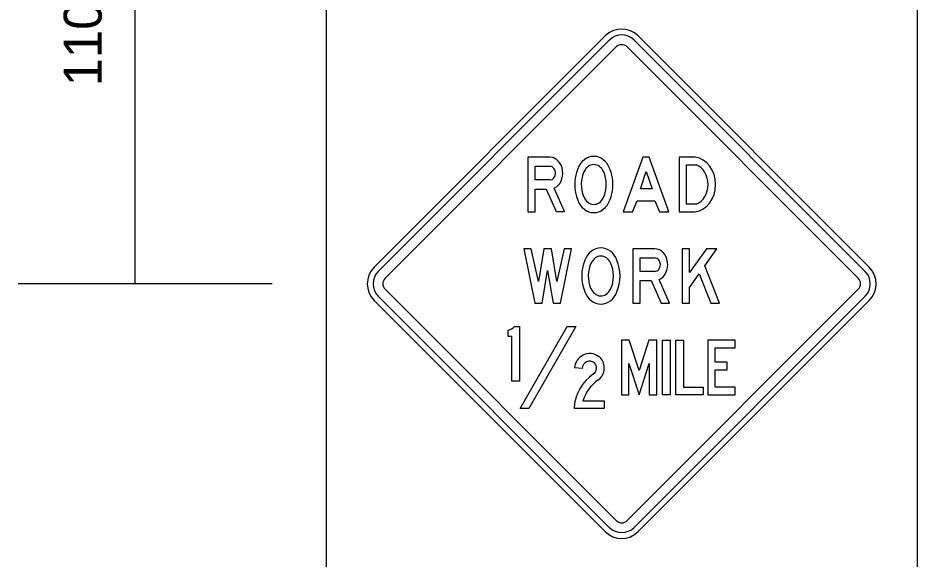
# Model space of a CAD drawing. Extents: x 1531.4 to 1538.6, y 1529.6 to 1539.7.
# Drawn here: x 1536.856 to 1538.277, y 1532.254 to 1533.108 of the extents above; entities that cross this region are included whole.
import ezdxf

# ---------------------------------------------------------------- set-up
doc = ezdxf.new("R2010")
doc.units = 0
for name, color, linetype in [('C-SIGN-FACE-N', 7, 'Continuous'), ('DETL-DIMS', 7, 'Continuous'), ('DETL-LINE', 7, 'Continuous'), ('DETL-NOTE', 7, 'Continuous')]:
    doc.layers.add(name, color=color, linetype=linetype)

msp = doc.modelspace()

# ---------------------------------------------------------------- linework, layer by layer
at = {"layer": 'C-SIGN-FACE-N'}
for p, q in [((1537.784, 1533.0799), (1537.4186, 1532.7145)), ((1538.2015, 1532.7145), (1537.8362, 1533.0799)), ((1537.8626, 1532.7079), (1537.8626, 1532.7079)), ((1537.784, 1532.297), (1537.4186, 1532.6623)), ((1538.2015, 1532.6623), (1537.8362, 1532.297)), ((1537.6308, 1532.6052), (1537.6308, 1532.6151)), ((1537.6308, 1532.6052), (1537.6308, 1532.6151)), ((1537.6308, 1532.6052), (1537.6308, 1532.6151)), ((1537.7474, 1532.5545), (1537.7354, 1532.5556)), ((1537.7474, 1532.5545), (1537.7354, 1532.5556)), ((1537.7474, 1532.5545), (1537.7354, 1532.5556)), ((1537.7474, 1532.5545), (1537.7474, 1532.5545)), ((1537.7474, 1532.5545), (1537.7474, 1532.5545)), ((1537.7474, 1532.5545), (1537.7474, 1532.5545)), ((1537.8297, 1532.3035), (1537.8451, 1532.319))]:
    msp.add_line(p, q, dxfattribs=at)
for points in [[(1537.7905, 1533.0734), (1537.4252, 1532.708)], [(1538.195, 1532.708), (1537.8297, 1533.0734)], [(1537.436, 1532.6971), (1537.8014, 1533.0625)], [(1537.8188, 1533.0625), (1538.1841, 1532.6971)], [(1537.6967, 1532.8883), (1537.6734, 1532.8883), (1537.6617, 1532.8883), (1537.6617, 1532.8022)], [(1537.8624, 1532.8196), (1537.8696, 1532.8022), (1537.8845, 1532.8022), (1537.8534, 1532.8883), (1537.8435, 1532.8883), (1537.8124, 1532.8022), (1537.8273, 1532.8022)], [(1537.9263, 1532.8883), (1537.9007, 1532.8883), (1537.9007, 1532.8022)], [(1537.6967, 1532.8524), (1537.6734, 1532.8524), (1537.6734, 1532.874), (1537.6967, 1532.874)], [(1537.9125, 1532.8144), (1537.9125, 1532.8762), (1537.9281, 1532.8762)], [(1537.6617, 1532.8022), (1537.6734, 1532.8022), (1537.6734, 1532.8381), (1537.6909, 1532.8381), (1537.7064, 1532.8024)], [(1537.7064, 1532.8024), (1537.7195, 1532.8024), (1537.7034, 1532.8396)], [(1537.8273, 1532.8022), (1537.8345, 1532.8196), (1537.8624, 1532.8196)], [(1537.9281, 1532.8144), (1537.9125, 1532.8144)], [(1537.9007, 1532.8022), (1537.9263, 1532.8022)], [(1537.8627, 1532.7438), (1537.8393, 1532.7438), (1537.8276, 1532.7438), (1537.8276, 1532.6577)], [(1537.8626, 1532.7079), (1537.8393, 1532.7079), (1537.8393, 1532.7294), (1537.8627, 1532.7294)], [(1537.8276, 1532.6577), (1537.8393, 1532.6577), (1537.8393, 1532.6935), (1537.8568, 1532.6935), (1537.8723, 1532.6578), (1537.8854, 1532.6578), (1537.8693, 1532.695)], [(1537.8014, 1532.3144), (1537.436, 1532.6797)], [(1538.1841, 1532.6797), (1537.8188, 1532.3144)], [(1537.4252, 1532.6689), (1537.7905, 1532.3035)], [(1537.8451, 1532.319), (1538.195, 1532.6689)], [(1537.6406, 1532.6208), (1537.6484, 1532.6208), (1537.6484, 1532.5347), (1537.6364, 1532.5347), (1537.6364, 1532.6052), (1537.6308, 1532.6052)], [(1537.6406, 1532.6208), (1537.6484, 1532.6208), (1537.6484, 1532.5347), (1537.6364, 1532.5347), (1537.6364, 1532.6052), (1537.6308, 1532.6052)], [(1537.6406, 1532.6208), (1537.6484, 1532.6208), (1537.6484, 1532.5347), (1537.6364, 1532.5347), (1537.6364, 1532.6052), (1537.6308, 1532.6052)], [(1537.7487, 1532.5037), (1537.7825, 1532.5037), (1537.7825, 1532.4916), (1537.7347, 1532.4916)], [(1537.7487, 1532.5037), (1537.7825, 1532.5037), (1537.7825, 1532.4916), (1537.7347, 1532.4916)], [(1537.7487, 1532.5037), (1537.7825, 1532.5037), (1537.7825, 1532.4916), (1537.7347, 1532.4916)], [(1537.8297, 1532.3035), (1537.8451, 1532.319)]]:
    msp.add_lwpolyline(points, dxfattribs=at)
for points in [[(1537.8583, 1532.8382), (1537.8397, 1532.8382), (1537.8485, 1532.8656)], [(1537.7307, 1532.7438), (1537.7189, 1532.7438), (1537.7075, 1532.6922), (1537.6992, 1532.7438), (1537.6868, 1532.7438), (1537.6784, 1532.6922), (1537.6671, 1532.7438), (1537.6553, 1532.7438), (1537.6725, 1532.6577), (1537.6843, 1532.6577), (1537.693, 1532.7093), (1537.7016, 1532.6577), (1537.7135, 1532.6577)], [(1537.9056, 1532.6577), (1537.9175, 1532.6577), (1537.9175, 1532.6824), (1537.9328, 1532.7044), (1537.9512, 1532.6577), (1537.9649, 1532.6577), (1537.9415, 1532.7169), (1537.9603, 1532.7438), (1537.9439, 1532.7438), (1537.9175, 1532.7061), (1537.9175, 1532.7438), (1537.9056, 1532.7438)], [(1537.7238, 1532.6208), (1537.7378, 1532.6208), (1537.6632, 1532.4916), (1537.6493, 1532.4916)], [(1537.7238, 1532.6208), (1537.7378, 1532.6208), (1537.6632, 1532.4916), (1537.6493, 1532.4916)], [(1537.7238, 1532.6208), (1537.7378, 1532.6208), (1537.6632, 1532.4916), (1537.6493, 1532.4916)], [(1537.8376, 1532.5131), (1537.8537, 1532.5627), (1537.8537, 1532.5131), (1537.8656, 1532.5131), (1537.8656, 1532.5992), (1537.8531, 1532.5992), (1537.8376, 1532.5516), (1537.8221, 1532.5992), (1537.8096, 1532.5992), (1537.8096, 1532.5131), (1537.8215, 1532.5131), (1537.8215, 1532.5627)], [(1537.8376, 1532.5131), (1537.8537, 1532.5627), (1537.8537, 1532.5131), (1537.8656, 1532.5131), (1537.8656, 1532.5992), (1537.8531, 1532.5992), (1537.8376, 1532.5516), (1537.8221, 1532.5992), (1537.8096, 1532.5992), (1537.8096, 1532.5131), (1537.8215, 1532.5131), (1537.8215, 1532.5627)], [(1537.8376, 1532.5131), (1537.8537, 1532.5627), (1537.8537, 1532.5131), (1537.8656, 1532.5131), (1537.8656, 1532.5992), (1537.8531, 1532.5992), (1537.8376, 1532.5516), (1537.8221, 1532.5992), (1537.8096, 1532.5992), (1537.8096, 1532.5131), (1537.8215, 1532.5131), (1537.8215, 1532.5627)], [(1537.8747, 1532.5992), (1537.8866, 1532.5992), (1537.8866, 1532.5131), (1537.8747, 1532.5131)], [(1537.8747, 1532.5992), (1537.8866, 1532.5992), (1537.8866, 1532.5131), (1537.8747, 1532.5131)], [(1537.8747, 1532.5992), (1537.8866, 1532.5992), (1537.8866, 1532.5131), (1537.8747, 1532.5131)], [(1537.8957, 1532.5992), (1537.9076, 1532.5992), (1537.9076, 1532.5252), (1537.9389, 1532.5252), (1537.9389, 1532.5131), (1537.8957, 1532.5131)], [(1537.8957, 1532.5992), (1537.9076, 1532.5992), (1537.9076, 1532.5252), (1537.9389, 1532.5252), (1537.9389, 1532.5131), (1537.8957, 1532.5131)], [(1537.8957, 1532.5992), (1537.9076, 1532.5992), (1537.9076, 1532.5252), (1537.9389, 1532.5252), (1537.9389, 1532.5131), (1537.8957, 1532.5131)], [(1537.958, 1532.5252), (1537.958, 1532.5527), (1537.9766, 1532.5527), (1537.9766, 1532.5648), (1537.958, 1532.5648), (1537.958, 1532.5872), (1537.9894, 1532.5872), (1537.9894, 1532.5992), (1537.9462, 1532.5992), (1537.9462, 1532.5131), (1537.9894, 1532.5131), (1537.9894, 1532.5252)], [(1537.958, 1532.5252), (1537.958, 1532.5527), (1537.9766, 1532.5527), (1537.9766, 1532.5648), (1537.958, 1532.5648), (1537.958, 1532.5872), (1537.9894, 1532.5872), (1537.9894, 1532.5992), (1537.9462, 1532.5992), (1537.9462, 1532.5131), (1537.9894, 1532.5131), (1537.9894, 1532.5252)], [(1537.958, 1532.5252), (1537.958, 1532.5527), (1537.9766, 1532.5527), (1537.9766, 1532.5648), (1537.958, 1532.5648), (1537.958, 1532.5872), (1537.9894, 1532.5872), (1537.9894, 1532.5992), (1537.9462, 1532.5992), (1537.9462, 1532.5131), (1537.9894, 1532.5131), (1537.9894, 1532.5252)]]:
    msp.add_lwpolyline(points, close=True, dxfattribs=at)
for centre, radius, start, end in [((1537.8101, 1533.0538), 0.0369, 45, 135), ((1537.8101, 1533.0538), 0.0277, 45, 135), ((1537.8101, 1533.0538), 0.0123, 45, 135), ((1537.4447, 1532.6884), 0.0369, 135, 225), ((1537.4447, 1532.6884), 0.0277, 135, 225), ((1538.1754, 1532.6884), 0.0277, 315, 45), ((1538.1754, 1532.6884), 0.0369, 315, 45), ((1537.4447, 1532.6884), 0.0123, 135, 225), ((1538.1754, 1532.6884), 0.0123, 315, 45), ((1537.6242, 1532.6377), 0.0236, 286.2525, 314.1302), ((1537.6242, 1532.6377), 0.0236, 286.2525, 314.1302), ((1537.6242, 1532.6377), 0.0236, 286.2525, 314.1302), ((1537.7595, 1532.5541), 0.0241, 54.3694, 176.4795), ((1537.7595, 1532.5541), 0.0241, 54.3694, 176.4795), ((1537.7595, 1532.5541), 0.0241, 54.3694, 176.4795), ((1537.7595, 1532.5541), 0.012, 51.4666, 178.1909), ((1537.7595, 1532.5541), 0.012, 51.4666, 178.1909), ((1537.7595, 1532.5541), 0.012, 51.4666, 178.1909), ((1537.7588, 1532.5554), 0.0116, 306.1354, 44.8873), ((1537.7588, 1532.5554), 0.0116, 306.1354, 44.8873), ((1537.7588, 1532.5554), 0.0116, 306.1354, 44.8873), ((1537.7622, 1532.5572), 0.0201, 3.3316, 55.5862), ((1537.7622, 1532.5572), 0.0201, 3.3316, 55.5862), ((1537.7622, 1532.5572), 0.0201, 3.3316, 55.5862), ((1537.7611, 1532.5546), 0.0215, 302.9934, 10.0902), ((1537.7611, 1532.5546), 0.0215, 302.9934, 10.0902), ((1537.7611, 1532.5546), 0.0215, 302.9934, 10.0902), ((1537.8045, 1532.488), 0.0699, 123.8618, 177.0151), ((1537.8045, 1532.488), 0.0699, 123.8618, 177.0151), ((1537.8045, 1532.488), 0.0699, 123.8618, 177.0151), ((1537.8096, 1532.4843), 0.0639, 125.1387, 162.3655), ((1537.8096, 1532.4843), 0.0639, 125.1387, 162.3655), ((1537.8096, 1532.4843), 0.0639, 125.1387, 162.3655), ((1537.8101, 1532.3231), 0.0123, 225, 315), ((1537.8101, 1532.3231), 0.0369, 225, 315), ((1537.8101, 1532.3231), 0.0277, 225, 315)]:
    msp.add_arc(centre, radius, start, end, dxfattribs=at)
for centre, major_axis, ratio, start_param, end_param in [((1537.6965, 1532.8632), (0, 0.0251), 0.813368, 3.487455, 6.269262), ((1537.766, 1532.8548), (0, 0.0349), 0.812335, 5.167056, 7.399315), ((1537.9231, 1532.8453), (0, 0.0432), 0.818392, 3.232708, 6.192058), ((1537.6965, 1532.8632), (0, 0.0108), 0.813368, 3.174143, 6.250457), ((1537.766, 1532.8548), (0, 0.0219), 0.812335, 5.251232, 7.315139), ((1537.9202, 1532.8453), (0, 0.0324), 0.818392, 3.446507, 5.978271), ((1537.7803, 1532.8453), (0, 0.0549), 0.812335, 1.101522, 2.04007), ((1537.7803, 1532.8453), (0, 0.042), 0.812335, 1.053076, 2.040122), ((1537.7516, 1532.8453), (0, 0.042), 0.812335, 4.194619, 5.230159), ((1537.7516, 1532.8453), (0, 0.0549), 0.812335, 4.243115, 5.181663), ((1537.766, 1532.8358), (0, 0.0349), 0.812335, 2.025463, 3.141593), ((1537.766, 1532.8358), (0, 0.0219), 0.812335, 2.025521, 3.099563), ((1537.766, 1532.8358), (0, 0.0219), 0.812335, 3.099563, 4.173604), ((1537.766, 1532.8358), (0, 0.0349), 0.812335, 3.141593, 4.257722), ((1537.7771, 1532.7103), (0, 0.0349), 0.812335, 5.167056, 7.399315), ((1537.7771, 1532.7103), (0, 0.0219), 0.812335, 5.251232, 7.315139), ((1537.8624, 1532.7187), (0, 0.0251), 0.813368, 3.487455, 6.268841), ((1537.7914, 1532.7007), (0, 0.0549), 0.812335, 1.101522, 2.04007), ((1537.7914, 1532.7007), (0, 0.042), 0.812335, 1.053076, 2.040122), ((1537.7628, 1532.7007), (0, 0.042), 0.812335, 4.194619, 5.230159), ((1537.7628, 1532.7007), (0, 0.0549), 0.812335, 4.243115, 5.181663), ((1537.8624, 1532.7187), (0, 0.0108), 0.813368, 3.174143, 6.249461), ((1537.7771, 1532.6912), (0, 0.0349), 0.812335, 2.025463, 3.141593), ((1537.7771, 1532.6912), (0, 0.0219), 0.812335, 2.025521, 3.099563), ((1537.7771, 1532.6912), (0, 0.0219), 0.812335, 3.099563, 4.173604), ((1537.7771, 1532.6912), (0, 0.0349), 0.812335, 3.141593, 4.257722)]:
    msp.add_ellipse(centre, major_axis=major_axis, ratio=ratio, start_param=start_param, end_param=end_param, dxfattribs=at)
at = {"layer": 'DETL-DIMS'}
for p, q in [((1537.0405, 1533.5312), (1537.0405, 1532.6884)), ((1537.2575, 1532.6884), (1536.8556, 1532.6884))]:
    msp.add_line(p, q, dxfattribs=at)
at = {"layer": 'DETL-LINE'}
msp.add_lwpolyline([(1537.3432, 1535.2018), (1538.277, 1535.2018), (1538.277, 1532.2226), (1537.3432, 1532.2226)], close=True, dxfattribs=at)

# ---------------------------------------------------------------- texts
at = {"layer": 'DETL-NOTE'}
msp.add_text("1100'", height=0.06, rotation=90, dxfattribs=at).set_placement((1536.9879, 1533.0004))

doc.saveas('drawing.dxf')
